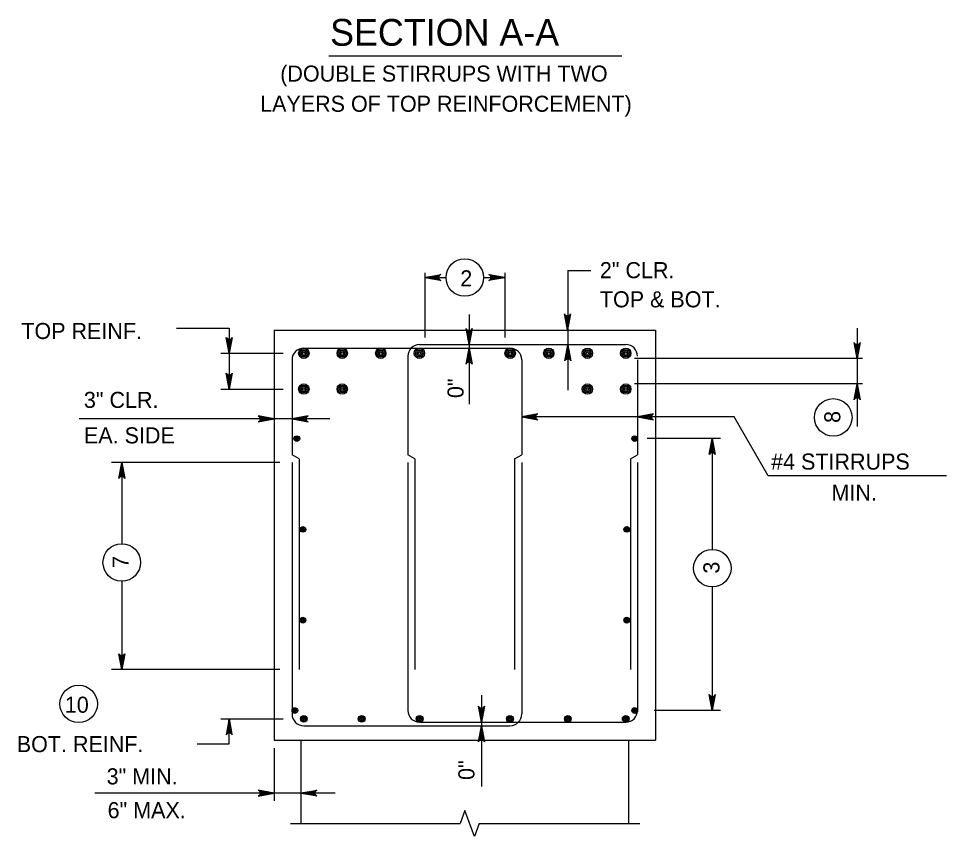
# Model space of a CAD drawing. Extents: x 646165 to 651486, y 296916 to 299292.
# Drawn here: x 648500.7 to 648673.8, y 298186.4 to 298339 of the extents above; entities that cross this region are included whole.
import ezdxf

# ---------------------------------------------------------------- set-up
doc = ezdxf.new("R2010")
doc.units = 0
for name, color, linetype in [('51', 7, 'Continuous'), ('52', 7, 'Continuous'), ('53', 7, 'Continuous'), ('54', 7, 'Continuous')]:
    doc.layers.add(name, color=color, linetype=linetype)

msp = doc.modelspace()

# ---------------------------------------------------------------- linework, layer by layer
at = {"layer": '51'}
for p, q in [((648548.38, 298280.85), (648548.38, 298204.38)), ((648548.38, 298280.85), (648619.5, 298280.85)), ((648619.5, 298280.85), (648619.5, 298204.38)), ((648548.38, 298204.38), (648619.5, 298204.38)), ((648553.38, 298204.38), (648553.38, 298188.8)), ((648614.5, 298204.38), (648614.5, 298188.8))]:
    msp.add_line(p, q, dxfattribs=at)
at = {"layer": '52'}
for p, q in [((648576.47, 298291.54), (648576.47, 298279.53)), ((648591.42, 298291.54), (648591.42, 298279.53)), ((648603.16, 298292.02), (648603.16, 298269.66)), ((648603.16, 298292.02), (648607.43, 298292.02)), ((648576.47, 298290.69), (648580.44, 298290.69)), ((648587.44, 298290.69), (648591.42, 298290.69)), ((648584.74, 298283.8), (648584.74, 298267.05)), ((648530.15, 298281.22), (648540.02, 298281.22)), ((648540.02, 298281.22), (648540.02, 298269.72)), ((648657.14, 298281.22), (648657.14, 298262.87)), ((648538.41, 298276.55), (648550.08, 298276.55)), ((648658.15, 298275.59), (648615.57, 298275.59)), ((648658.15, 298270.85), (648615.57, 298270.85)), ((648538.41, 298269.89), (648550.08, 298269.89)), ((648558.77, 298264.3), (648512.03, 298264.3)), ((648634.21, 298264.69), (648594.57, 298264.69)), ((648640.56, 298253.7), (648634.21, 298264.69)), ((648631.66, 298260.63), (648617.93, 298260.63)), ((648630.11, 298260.63), (648630.11, 298239.96)), ((648549.42, 298256.19), (648518.02, 298256.19)), ((648519.96, 298256.19), (648519.96, 298241.02)), ((648673.78, 298253.7), (648640.56, 298253.7)), ((648519.96, 298234.02), (648519.96, 298217.52)), ((648630.11, 298232.96), (648630.11, 298209.88)), ((648549.42, 298217.52), (648518.02, 298217.52)), ((648587.03, 298212.75), (648587.03, 298195.74)), ((648631.66, 298209.88), (648619.24, 298209.88)), ((648538.41, 298208.35), (648550.08, 298208.35)), ((648540.02, 298203.68), (648540.02, 298208.35)), ((648534.03, 298203.68), (648540.02, 298203.68)), ((648548.38, 298202.9), (648548.38, 298193.02)), ((648559.79, 298194.5), (648514.94, 298194.5)), ((648551.41, 298188.8), (648583.11, 298188.8)), ((648586.61, 298188.8), (648616.57, 298188.8))]:
    msp.add_line(p, q, dxfattribs=at)
for points in [[(648576.47, 298290.69), (648579.46, 298291.25), (648579.34, 298291.17), (648579.23, 298291.09), (648579.17, 298290.99), (648579.11, 298290.89), (648579.09, 298290.79), (648579.07, 298290.69), (648579.09, 298290.59), (648579.11, 298290.49), (648579.17, 298290.39), (648579.23, 298290.29), (648579.34, 298290.21), (648579.46, 298290.13), (648576.47, 298290.69), (648579.34, 298290.21), (648579.23, 298290.29), (648576.47, 298290.69), (648579.17, 298290.39), (648579.11, 298290.49), (648576.47, 298290.69), (648579.09, 298290.59), (648579.07, 298290.69), (648576.47, 298290.69), (648579.09, 298290.79), (648579.11, 298290.89), (648576.47, 298290.69), (648579.17, 298290.99), (648579.23, 298291.09), (648576.47, 298290.69), (648579.34, 298291.17)], [(648591.42, 298290.69), (648588.44, 298290.13), (648588.55, 298290.21), (648588.67, 298290.29), (648588.73, 298290.39), (648588.79, 298290.49), (648588.81, 298290.59), (648588.82, 298290.69), (648588.81, 298290.79), (648588.79, 298290.89), (648588.73, 298290.99), (648588.67, 298291.09), (648588.55, 298291.17), (648588.44, 298291.25), (648591.42, 298290.69), (648588.55, 298291.17), (648588.67, 298291.09), (648591.42, 298290.69), (648588.73, 298290.99), (648588.79, 298290.89), (648591.42, 298290.69), (648588.81, 298290.79), (648588.82, 298290.69), (648591.42, 298290.69), (648588.81, 298290.59), (648588.79, 298290.49), (648591.42, 298290.69), (648588.73, 298290.39), (648588.67, 298290.29), (648591.42, 298290.69), (648588.55, 298290.21)], [(648603.11, 298280.93), (648602.55, 298283.91), (648602.63, 298283.8), (648602.71, 298283.68), (648602.81, 298283.62), (648602.91, 298283.56), (648603.01, 298283.55), (648603.11, 298283.53), (648603.21, 298283.55), (648603.31, 298283.56), (648603.41, 298283.62), (648603.51, 298283.68), (648603.59, 298283.8), (648603.67, 298283.91), (648603.11, 298280.93), (648603.59, 298283.8), (648603.51, 298283.68), (648603.11, 298280.93), (648603.41, 298283.62), (648603.31, 298283.56), (648603.11, 298280.93), (648603.21, 298283.55), (648603.11, 298283.53), (648603.11, 298280.93), (648603.01, 298283.55), (648602.91, 298283.56), (648603.11, 298280.93), (648602.81, 298283.62), (648602.71, 298283.68), (648603.11, 298280.93), (648602.63, 298283.8)], [(648584.74, 298278.19), (648584.18, 298281.17), (648584.26, 298281.05), (648584.34, 298280.94), (648584.44, 298280.88), (648584.54, 298280.82), (648584.64, 298280.8), (648584.74, 298280.79), (648584.84, 298280.8), (648584.94, 298280.82), (648585.04, 298280.88), (648585.14, 298280.94), (648585.22, 298281.05), (648585.3, 298281.17), (648584.74, 298278.19), (648585.22, 298281.05), (648585.14, 298280.94), (648584.74, 298278.19), (648585.04, 298280.88), (648584.94, 298280.82), (648584.74, 298278.19), (648584.84, 298280.8), (648584.74, 298280.79), (648584.74, 298278.19), (648584.64, 298280.8), (648584.54, 298280.82), (648584.74, 298278.19), (648584.44, 298280.88), (648584.34, 298280.94), (648584.74, 298278.19), (648584.26, 298281.05)], [(648540.02, 298276.55), (648539.46, 298279.53), (648539.54, 298279.42), (648539.62, 298279.3), (648539.72, 298279.25), (648539.82, 298279.19), (648539.92, 298279.17), (648540.02, 298279.15), (648540.12, 298279.17), (648540.22, 298279.19), (648540.32, 298279.25), (648540.42, 298279.3), (648540.5, 298279.42), (648540.58, 298279.53), (648540.02, 298276.55), (648540.5, 298279.42), (648540.42, 298279.3), (648540.02, 298276.55), (648540.32, 298279.25), (648540.22, 298279.19), (648540.02, 298276.55), (648540.12, 298279.17), (648540.02, 298279.15), (648540.02, 298276.55), (648539.92, 298279.17), (648539.82, 298279.19), (648540.02, 298276.55), (648539.72, 298279.25), (648539.62, 298279.3), (648540.02, 298276.55), (648539.54, 298279.42)], [(648584.74, 298277.52), (648585.3, 298274.54), (648585.22, 298274.65), (648585.14, 298274.77), (648585.04, 298274.82), (648584.94, 298274.88), (648584.84, 298274.9), (648584.74, 298274.92), (648584.64, 298274.9), (648584.54, 298274.88), (648584.44, 298274.82), (648584.34, 298274.77), (648584.26, 298274.65), (648584.18, 298274.54), (648584.74, 298277.52), (648584.26, 298274.65), (648584.34, 298274.77), (648584.74, 298277.52), (648584.44, 298274.82), (648584.54, 298274.88), (648584.74, 298277.52), (648584.64, 298274.9), (648584.74, 298274.92), (648584.74, 298277.52), (648584.84, 298274.9), (648584.94, 298274.88), (648584.74, 298277.52), (648585.04, 298274.82), (648585.14, 298274.77), (648584.74, 298277.52), (648585.22, 298274.65)], [(648603.16, 298278.12), (648603.72, 298275.14), (648603.64, 298275.26), (648603.56, 298275.37), (648603.46, 298275.43), (648603.36, 298275.49), (648603.26, 298275.51), (648603.16, 298275.52), (648603.06, 298275.51), (648602.96, 298275.49), (648602.86, 298275.43), (648602.76, 298275.37), (648602.68, 298275.26), (648602.6, 298275.14), (648603.16, 298278.12), (648602.68, 298275.26), (648602.76, 298275.37), (648603.16, 298278.12), (648602.86, 298275.43), (648602.96, 298275.49), (648603.16, 298278.12), (648603.06, 298275.51), (648603.16, 298275.52), (648603.16, 298278.12), (648603.26, 298275.51), (648603.36, 298275.49), (648603.16, 298278.12), (648603.46, 298275.43), (648603.56, 298275.37), (648603.16, 298278.12), (648603.64, 298275.26)], [(648657.14, 298275.59), (648656.58, 298278.57), (648656.66, 298278.45), (648656.74, 298278.34), (648656.84, 298278.28), (648656.94, 298278.22), (648657.04, 298278.2), (648657.14, 298278.19), (648657.24, 298278.2), (648657.34, 298278.22), (648657.44, 298278.28), (648657.54, 298278.34), (648657.62, 298278.45), (648657.7, 298278.57), (648657.14, 298275.59), (648657.62, 298278.45), (648657.54, 298278.34), (648657.14, 298275.59), (648657.44, 298278.28), (648657.34, 298278.22), (648657.14, 298275.59), (648657.24, 298278.2), (648657.14, 298278.19), (648657.14, 298275.59), (648657.04, 298278.2), (648656.94, 298278.22), (648657.14, 298275.59), (648656.84, 298278.28), (648656.74, 298278.34), (648657.14, 298275.59), (648656.66, 298278.45)], [(648540.02, 298269.89), (648539.46, 298272.87), (648539.54, 298272.75), (648539.62, 298272.64), (648539.72, 298272.58), (648539.82, 298272.52), (648539.92, 298272.5), (648540.02, 298272.49), (648540.12, 298272.5), (648540.22, 298272.52), (648540.32, 298272.58), (648540.42, 298272.64), (648540.5, 298272.75), (648540.58, 298272.87), (648540.02, 298269.89), (648540.5, 298272.75), (648540.42, 298272.64), (648540.02, 298269.89), (648540.32, 298272.58), (648540.22, 298272.52), (648540.02, 298269.89), (648540.12, 298272.5), (648540.02, 298272.49), (648540.02, 298269.89), (648539.92, 298272.5), (648539.82, 298272.52), (648540.02, 298269.89), (648539.72, 298272.58), (648539.62, 298272.64), (648540.02, 298269.89), (648539.54, 298272.75)], [(648657.14, 298270.85), (648657.7, 298267.87), (648657.62, 298267.98), (648657.54, 298268.1), (648657.44, 298268.16), (648657.34, 298268.22), (648657.24, 298268.23), (648657.14, 298268.25), (648657.04, 298268.23), (648656.94, 298268.22), (648656.84, 298268.16), (648656.74, 298268.1), (648656.66, 298267.98), (648656.58, 298267.87), (648657.14, 298270.85), (648656.66, 298267.98), (648656.74, 298268.1), (648657.14, 298270.85), (648656.84, 298268.16), (648656.94, 298268.22), (648657.14, 298270.85), (648657.04, 298268.23), (648657.14, 298268.25), (648657.14, 298270.85), (648657.24, 298268.23), (648657.34, 298268.22), (648657.14, 298270.85), (648657.44, 298268.16), (648657.54, 298268.1), (648657.14, 298270.85), (648657.62, 298267.98)], [(648594.57, 298264.69), (648597.55, 298264.13), (648597.44, 298264.21), (648597.32, 298264.29), (648597.26, 298264.39), (648597.21, 298264.49), (648597.19, 298264.59), (648597.17, 298264.69), (648597.19, 298264.79), (648597.21, 298264.89), (648597.26, 298264.99), (648597.32, 298265.09), (648597.44, 298265.17), (648597.55, 298265.25), (648594.57, 298264.69), (648597.44, 298265.17), (648597.32, 298265.09), (648594.57, 298264.69), (648597.26, 298264.99), (648597.21, 298264.89), (648594.57, 298264.69), (648597.19, 298264.79), (648597.17, 298264.69), (648594.57, 298264.69), (648597.19, 298264.59), (648597.21, 298264.49), (648594.57, 298264.69), (648597.26, 298264.39), (648597.32, 298264.29), (648594.57, 298264.69), (648597.44, 298264.21)], [(648616.17, 298264.69), (648619.15, 298264.13), (648619.04, 298264.21), (648618.92, 298264.29), (648618.86, 298264.39), (648618.81, 298264.49), (648618.79, 298264.59), (648618.77, 298264.69), (648618.79, 298264.79), (648618.81, 298264.89), (648618.86, 298264.99), (648618.92, 298265.09), (648619.04, 298265.17), (648619.15, 298265.25), (648616.17, 298264.69), (648619.04, 298265.17), (648618.92, 298265.09), (648616.17, 298264.69), (648618.86, 298264.99), (648618.81, 298264.89), (648616.17, 298264.69), (648618.79, 298264.79), (648618.77, 298264.69), (648616.17, 298264.69), (648618.79, 298264.59), (648618.81, 298264.49), (648616.17, 298264.69), (648618.86, 298264.39), (648618.92, 298264.29), (648616.17, 298264.69), (648619.04, 298264.21)], [(648548.38, 298264.3), (648545.4, 298264.86), (648545.52, 298264.78), (648545.63, 298264.7), (648545.69, 298264.6), (648545.75, 298264.5), (648545.77, 298264.4), (648545.78, 298264.3), (648545.77, 298264.2), (648545.75, 298264.1), (648545.69, 298264), (648545.63, 298263.9), (648545.52, 298263.82), (648545.4, 298263.74), (648548.38, 298264.3), (648545.52, 298263.82), (648545.63, 298263.9), (648548.38, 298264.3), (648545.69, 298264), (648545.75, 298264.1), (648548.38, 298264.3), (648545.77, 298264.2), (648545.78, 298264.3), (648548.38, 298264.3), (648545.77, 298264.4), (648545.75, 298264.5), (648548.38, 298264.3), (648545.69, 298264.6), (648545.63, 298264.7), (648548.38, 298264.3), (648545.52, 298264.78)], [(648551.72, 298264.3), (648554.7, 298263.74), (648554.59, 298263.82), (648554.47, 298263.9), (648554.41, 298264), (648554.35, 298264.1), (648554.33, 298264.2), (648554.32, 298264.3), (648554.33, 298264.4), (648554.35, 298264.5), (648554.41, 298264.6), (648554.47, 298264.7), (648554.59, 298264.78), (648554.7, 298264.86), (648551.72, 298264.3), (648554.59, 298264.78), (648554.47, 298264.7), (648551.72, 298264.3), (648554.41, 298264.6), (648554.35, 298264.5), (648551.72, 298264.3), (648554.33, 298264.4), (648554.32, 298264.3), (648551.72, 298264.3), (648554.33, 298264.2), (648554.35, 298264.1), (648551.72, 298264.3), (648554.41, 298264), (648554.47, 298263.9), (648551.72, 298264.3), (648554.59, 298263.82)], [(648630.11, 298260.63), (648630.67, 298257.65), (648630.59, 298257.76), (648630.51, 298257.88), (648630.41, 298257.94), (648630.31, 298258), (648630.21, 298258.01), (648630.11, 298258.03), (648630.01, 298258.01), (648629.91, 298258), (648629.81, 298257.94), (648629.71, 298257.88), (648629.63, 298257.76), (648629.55, 298257.65), (648630.11, 298260.63), (648629.63, 298257.76), (648629.71, 298257.88), (648630.11, 298260.63), (648629.81, 298257.94), (648629.91, 298258), (648630.11, 298260.63), (648630.01, 298258.01), (648630.11, 298258.03), (648630.11, 298260.63), (648630.21, 298258.01), (648630.31, 298258), (648630.11, 298260.63), (648630.41, 298257.94), (648630.51, 298257.88), (648630.11, 298260.63), (648630.59, 298257.76)], [(648519.96, 298256.19), (648520.51, 298253.2), (648520.43, 298253.32), (648520.36, 298253.43), (648520.26, 298253.49), (648520.16, 298253.55), (648520.06, 298253.57), (648519.96, 298253.59), (648519.86, 298253.57), (648519.76, 298253.55), (648519.66, 298253.49), (648519.56, 298253.43), (648519.48, 298253.32), (648519.4, 298253.2), (648519.96, 298256.19), (648519.48, 298253.32), (648519.56, 298253.43), (648519.96, 298256.19), (648519.66, 298253.49), (648519.76, 298253.55), (648519.96, 298256.19), (648519.86, 298253.57), (648519.96, 298253.59), (648519.96, 298256.19), (648520.06, 298253.57), (648520.16, 298253.55), (648519.96, 298256.19), (648520.26, 298253.49), (648520.36, 298253.43), (648519.96, 298256.19), (648520.43, 298253.32)], [(648519.96, 298217.52), (648519.4, 298220.5), (648519.48, 298220.39), (648519.56, 298220.27), (648519.66, 298220.21), (648519.76, 298220.15), (648519.86, 298220.14), (648519.96, 298220.12), (648520.06, 298220.14), (648520.16, 298220.15), (648520.26, 298220.21), (648520.36, 298220.27), (648520.43, 298220.39), (648520.51, 298220.5), (648519.96, 298217.52), (648520.43, 298220.39), (648520.36, 298220.27), (648519.96, 298217.52), (648520.26, 298220.21), (648520.16, 298220.15), (648519.96, 298217.52), (648520.06, 298220.14), (648519.96, 298220.12), (648519.96, 298217.52), (648519.86, 298220.14), (648519.76, 298220.15), (648519.96, 298217.52), (648519.66, 298220.21), (648519.56, 298220.27), (648519.96, 298217.52), (648519.48, 298220.39)], [(648630.11, 298209.88), (648629.55, 298212.87), (648629.63, 298212.75), (648629.71, 298212.64), (648629.81, 298212.58), (648629.91, 298212.52), (648630.01, 298212.5), (648630.11, 298212.48), (648630.21, 298212.5), (648630.31, 298212.52), (648630.41, 298212.58), (648630.51, 298212.64), (648630.59, 298212.75), (648630.67, 298212.87), (648630.11, 298209.88), (648630.59, 298212.75), (648630.51, 298212.64), (648630.11, 298209.88), (648630.41, 298212.58), (648630.31, 298212.52), (648630.11, 298209.88), (648630.21, 298212.5), (648630.11, 298212.48), (648630.11, 298209.88), (648630.01, 298212.5), (648629.91, 298212.52), (648630.11, 298209.88), (648629.81, 298212.58), (648629.71, 298212.64), (648630.11, 298209.88), (648629.63, 298212.75)], [(648587.03, 298207.72), (648586.47, 298210.7), (648586.55, 298210.59), (648586.63, 298210.47), (648586.73, 298210.41), (648586.83, 298210.35), (648586.93, 298210.33), (648587.03, 298210.32), (648587.13, 298210.33), (648587.23, 298210.35), (648587.33, 298210.41), (648587.43, 298210.47), (648587.51, 298210.59), (648587.59, 298210.7), (648587.03, 298207.72), (648587.51, 298210.59), (648587.43, 298210.47), (648587.03, 298207.72), (648587.33, 298210.41), (648587.23, 298210.35), (648587.03, 298207.72), (648587.13, 298210.33), (648587.03, 298210.32), (648587.03, 298207.72), (648586.93, 298210.33), (648586.83, 298210.35), (648587.03, 298207.72), (648586.73, 298210.41), (648586.63, 298210.47), (648587.03, 298207.72), (648586.55, 298210.59)], [(648540.02, 298208.35), (648539.46, 298205.37), (648539.54, 298205.48), (648539.62, 298205.6), (648539.72, 298205.66), (648539.82, 298205.72), (648539.92, 298205.73), (648540.02, 298205.75), (648540.12, 298205.73), (648540.22, 298205.72), (648540.32, 298205.66), (648540.42, 298205.6), (648540.5, 298205.48), (648540.58, 298205.37), (648540.02, 298208.35), (648540.5, 298205.48), (648540.42, 298205.6), (648540.02, 298208.35), (648540.32, 298205.66), (648540.22, 298205.72), (648540.02, 298208.35), (648540.12, 298205.73), (648540.02, 298205.75), (648540.02, 298208.35), (648539.92, 298205.73), (648539.82, 298205.72), (648540.02, 298208.35), (648539.72, 298205.66), (648539.62, 298205.6), (648540.02, 298208.35), (648539.54, 298205.48)], [(648587.03, 298207.05), (648587.59, 298204.07), (648587.51, 298204.18), (648587.43, 298204.3), (648587.33, 298204.36), (648587.23, 298204.42), (648587.13, 298204.43), (648587.03, 298204.45), (648586.93, 298204.43), (648586.83, 298204.42), (648586.73, 298204.36), (648586.63, 298204.3), (648586.55, 298204.18), (648586.47, 298204.07), (648587.03, 298207.05), (648586.55, 298204.18), (648586.63, 298204.3), (648587.03, 298207.05), (648586.73, 298204.36), (648586.83, 298204.42), (648587.03, 298207.05), (648586.93, 298204.43), (648587.03, 298204.45), (648587.03, 298207.05), (648587.13, 298204.43), (648587.23, 298204.42), (648587.03, 298207.05), (648587.33, 298204.36), (648587.43, 298204.3), (648587.03, 298207.05), (648587.51, 298204.18)], [(648548.38, 298194.5), (648545.4, 298195.06), (648545.52, 298194.98), (648545.63, 298194.9), (648545.69, 298194.8), (648545.75, 298194.7), (648545.77, 298194.6), (648545.78, 298194.5), (648545.77, 298194.4), (648545.75, 298194.3), (648545.69, 298194.2), (648545.63, 298194.1), (648545.52, 298194.02), (648545.4, 298193.94), (648548.38, 298194.5), (648545.52, 298194.02), (648545.63, 298194.1), (648548.38, 298194.5), (648545.69, 298194.2), (648545.75, 298194.3), (648548.38, 298194.5), (648545.77, 298194.4), (648545.78, 298194.5), (648548.38, 298194.5), (648545.77, 298194.6), (648545.75, 298194.7), (648548.38, 298194.5), (648545.69, 298194.8), (648545.63, 298194.9), (648548.38, 298194.5), (648545.52, 298194.98)], [(648553.38, 298194.5), (648556.37, 298195.06), (648556.25, 298194.98), (648556.14, 298194.9), (648556.08, 298194.8), (648556.02, 298194.7), (648556, 298194.6), (648555.98, 298194.5), (648556, 298194.4), (648556.02, 298194.3), (648556.08, 298194.2), (648556.14, 298194.1), (648556.25, 298194.02), (648556.37, 298193.94), (648553.38, 298194.5), (648556.25, 298194.02), (648556.14, 298194.1), (648553.38, 298194.5), (648556.08, 298194.2), (648556.02, 298194.3), (648553.38, 298194.5), (648556, 298194.4), (648555.98, 298194.5), (648553.38, 298194.5), (648556, 298194.6), (648556.02, 298194.7), (648553.38, 298194.5), (648556.08, 298194.8), (648556.14, 298194.9), (648553.38, 298194.5), (648556.25, 298194.98)], [(648586.61, 298188.8), (648585.73, 298186.4), (648583.98, 298191.21), (648583.11, 298188.8)]]:
    msp.add_lwpolyline(points, dxfattribs=at)
for centre in [(648583.94, 298290.69), (648652.67, 298264.59), (648519.96, 298237.52), (648630.11, 298236.46), (648511.92, 298211.13)]:
    msp.add_circle(centre, 3.5, dxfattribs=at)
at = {"layer": '53'}
msp.add_line((648558.58, 298332.09), (648613.25, 298332.09), dxfattribs=at)
at = {"layer": '54'}
for p, q in [((648553.92, 298277.52), (648592.37, 298277.52)), ((648575.52, 298278.19), (648613.97, 298278.19)), ((648573.32, 298275.99), (648573.32, 298257.62)), ((648551.72, 298275.32), (648551.72, 298257.62)), ((648594.57, 298275.32), (648594.57, 298257.62)), ((648616.17, 298275.32), (648616.17, 298257.62)), ((648553.05, 298256.85), (648551.72, 298257.62)), ((648553.05, 298256.85), (648553.05, 298217.52)), ((648574.65, 298256.85), (648573.32, 298257.62)), ((648574.65, 298256.85), (648574.65, 298217.52)), ((648593.24, 298256.85), (648594.57, 298257.62)), ((648593.24, 298256.85), (648593.24, 298217.52)), ((648614.84, 298256.85), (648616.17, 298257.62)), ((648614.84, 298256.85), (648614.84, 298217.52)), ((648551.72, 298256.19), (648551.72, 298209.24)), ((648573.32, 298256.19), (648573.32, 298209.92)), ((648594.57, 298256.19), (648594.57, 298209.25)), ((648616.17, 298256.19), (648616.17, 298209.92)), ((648553.92, 298207.05), (648592.37, 298207.05)), ((648575.52, 298207.72), (648613.97, 298207.72))]:
    msp.add_line(p, q, dxfattribs=at)
for centre, radius in [((648553.92, 298276.55), 0.967), ((648561.08, 298276.55), 0.967), ((648568.28, 298276.55), 0.967), ((648575.48, 298276.55), 0.967), ((648592.41, 298276.55), 0.967), ((648599.61, 298276.55), 0.967), ((648606.81, 298276.55), 0.967), ((648613.97, 298276.55), 0.967), ((648553.92, 298276.55), 0.725), ((648553.92, 298276.55), 0.483), ((648553.92, 298276.55), 0.242), ((648561.08, 298276.55), 0.725), ((648561.08, 298276.55), 0.483), ((648561.08, 298276.55), 0.242), ((648568.28, 298276.55), 0.725), ((648568.28, 298276.55), 0.483), ((648568.28, 298276.55), 0.242), ((648575.48, 298276.55), 0.725), ((648575.48, 298276.55), 0.483), ((648575.48, 298276.55), 0.242), ((648592.41, 298276.55), 0.725), ((648592.41, 298276.55), 0.483), ((648592.41, 298276.55), 0.242), ((648599.61, 298276.55), 0.725), ((648599.61, 298276.55), 0.483), ((648599.61, 298276.55), 0.242), ((648606.81, 298276.55), 0.725), ((648606.81, 298276.55), 0.483), ((648606.81, 298276.55), 0.242), ((648613.97, 298276.55), 0.725), ((648613.97, 298276.55), 0.483), ((648613.97, 298276.55), 0.242), ((648553.92, 298269.89), 0.967), ((648553.92, 298269.89), 0.725), ((648561.08, 298269.89), 0.967), ((648561.08, 298269.89), 0.725), ((648606.81, 298269.89), 0.967), ((648606.81, 298269.89), 0.725), ((648613.97, 298269.89), 0.967), ((648613.97, 298269.89), 0.725), ((648553.92, 298269.89), 0.483), ((648553.92, 298269.89), 0.242), ((648561.08, 298269.89), 0.483), ((648561.08, 298269.89), 0.242), ((648606.81, 298269.89), 0.483), ((648606.81, 298269.89), 0.242), ((648613.97, 298269.89), 0.483), ((648613.97, 298269.89), 0.242), ((648552.62, 298260.63), 0.533), ((648552.62, 298260.63), 0.4), ((648552.62, 298260.63), 0.267), ((648552.62, 298260.63), 0.133), ((648615.64, 298260.63), 0.533), ((648615.64, 298260.63), 0.4), ((648615.64, 298260.63), 0.267), ((648615.64, 298260.63), 0.133), ((648553.74, 298243.7), 0.533), ((648553.74, 298243.7), 0.4), ((648553.74, 298243.7), 0.267), ((648553.74, 298243.7), 0.133), ((648614.15, 298243.7), 0.533), ((648614.15, 298243.7), 0.4), ((648614.15, 298243.7), 0.267), ((648614.15, 298243.7), 0.133), ((648553.74, 298226.76), 0.533), ((648553.74, 298226.76), 0.4), ((648614.15, 298226.76), 0.533), ((648614.15, 298226.76), 0.4), ((648553.74, 298226.76), 0.267), ((648553.74, 298226.76), 0.133), ((648614.15, 298226.76), 0.267), ((648614.15, 298226.76), 0.133), ((648552.25, 298209.88), 0.533), ((648552.25, 298209.88), 0.4), ((648552.25, 298209.88), 0.267), ((648552.25, 298209.88), 0.133), ((648615.64, 298209.88), 0.533), ((648615.64, 298209.88), 0.4), ((648615.64, 298209.88), 0.267), ((648615.64, 298209.88), 0.133), ((648553.92, 298208.35), 0.633), ((648553.92, 298208.35), 0.475), ((648553.92, 298208.35), 0.317), ((648553.92, 298208.35), 0.158), ((648564.72, 298208.35), 0.633), ((648564.72, 298208.35), 0.475), ((648564.72, 298208.35), 0.317), ((648564.72, 298208.35), 0.158), ((648575.52, 298208.35), 0.633), ((648575.52, 298208.35), 0.475), ((648575.52, 298208.35), 0.317), ((648575.52, 298208.35), 0.158), ((648592.37, 298208.35), 0.633), ((648592.37, 298208.35), 0.475), ((648592.37, 298208.35), 0.317), ((648592.37, 298208.35), 0.158), ((648603.17, 298208.35), 0.633), ((648603.17, 298208.35), 0.475), ((648603.17, 298208.35), 0.317), ((648603.17, 298208.35), 0.158), ((648613.97, 298208.35), 0.633), ((648613.97, 298208.35), 0.475), ((648613.97, 298208.35), 0.317), ((648613.97, 298208.35), 0.158)]:
    msp.add_circle(centre, radius, dxfattribs=at)
for centre, start, end in [((648553.92, 298275.32), 90, 180), ((648575.52, 298275.99), 90, 180), ((648592.37, 298275.32), 0, 90), ((648613.97, 298275.99), 0, 90), ((648575.52, 298209.92), 180, 270), ((648613.97, 298209.92), 270, 360), ((648553.92, 298209.25), 180.2988, 270), ((648592.37, 298209.25), 270, 0)]:
    msp.add_arc(centre, 2.2, start, end, dxfattribs=at)

# ---------------------------------------------------------------- texts
at = {"layer": '53'}
for s, height, p in [('SECTION A-A', 5, (648558.82, 298333.94)), ('(DOUBLE STIRRUPS WITH TWO', 3, (648549.52, 298327.25)), ('LAYERS OF TOP REINFORCEMENT)', 3, (648545.77, 298321.62)), ('2" CLR.', 3, (648609.14, 298290.57)), ('2', 3, (648583.1, 298289.04)), ('TOP & BOT.', 3, (648609.14, 298285.13)), ('TOP REINF.', 3, (648501.23, 298279.22)), ('3" CLR.', 3, (648512.9, 298266.36)), ('EA. SIDE', 3, (648512.91, 298259.74)), ('#4 STIRRUPS', 3, (648641.08, 298254.85)), ('MIN.', 3, (648652.34, 298249.07)), ('10', 3, (648509.34, 298209.48)), ('BOT. REINF.', 3, (648500.38, 298202.13)), ('3" MIN.', 3, (648517.14, 298196.11)), ('6" MAX.', 3, (648517.32, 298189.8))]:
    msp.add_text(s, height=height, dxfattribs=at).set_placement(p)
for s, p in [('0"', (648583.72, 298268.2)), ('8', (648653.99, 298263.56)), ('7', (648521.28, 298236.49)), ('3', (648631.44, 298235.44)), ('0"', (648585.74, 298196.94))]:
    msp.add_text(s, height=3, rotation=90, dxfattribs=at).set_placement(p)

doc.saveas('drawing.dxf')
